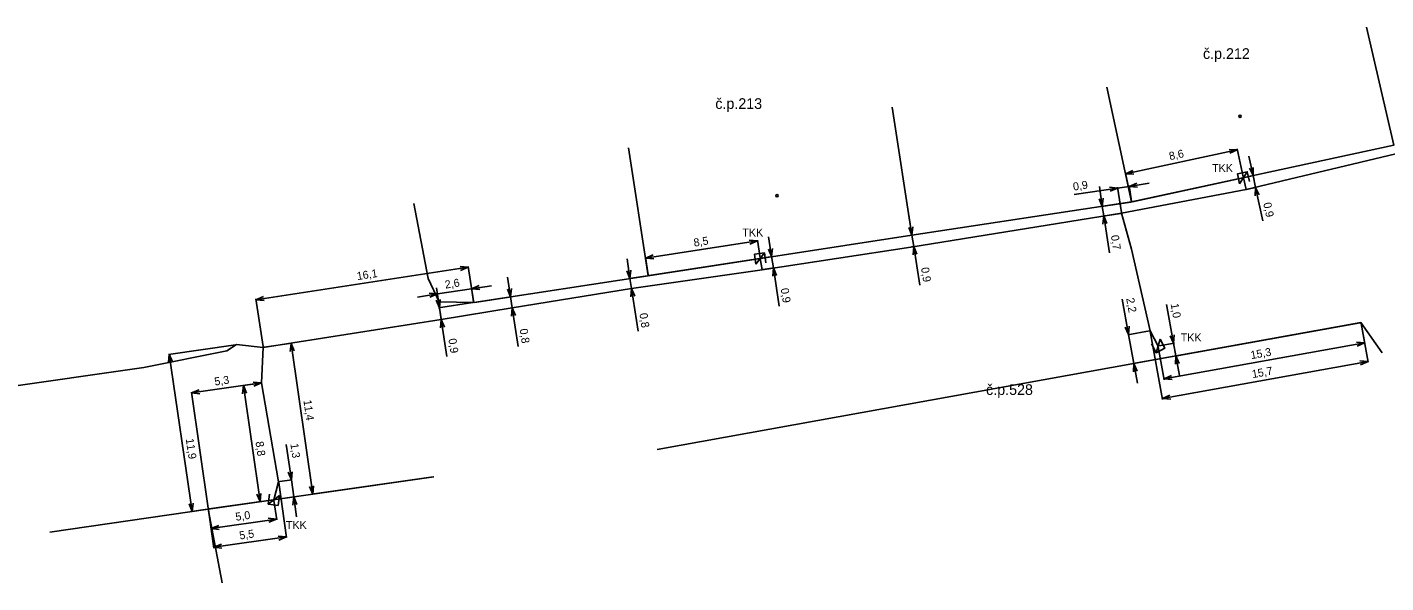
# Model space of a CAD drawing. Extents: x -770877 to -770229, y -1050342 to -1050226.
# Drawn here: x -770486.4 to -770384.5, y -1050339.6 to -1050298 of the extents above; entities that cross this region are included whole.
import ezdxf

# ---------------------------------------------------------------- set-up
doc = ezdxf.new("R2010")
doc.units = 0
for name, color, linetype in [('f001_pol_linie', 7, 'Continuous'), ('f001_pol_znacky', 7, 'Continuous'), ('f003_opt_sit_texty', 7, 'Continuous'), ('f003_opt_sit_znacky', 7, 'Continuous'), ('f006_osa_trasy', 7, 'Continuous'), ('f006_stp_koty', 7, 'Continuous'), ('Inspire adresy', 7, 'Continuous')]:
    doc.layers.add(name, color=color, linetype=linetype)

msp = doc.modelspace()

# ---------------------------------------------------------------- linework, layer by layer
at = {"layer": 'f001_pol_linie'}
for points in [[(-770405.45, -1050302.49), (-770403.58, -1050311.09), (-770383.92, -1050306.82), (-770385.97, -1050297.98)], [(-770441.3, -1050307.04), (-770439.82, -1050316.62), (-770420.05, -1050313.57), (-770421.53, -1050303.99)], [(-770457.38, -1050311.2), (-770456.32, -1050316.84), (-770455.49, -1050318.59), (-770452.9, -1050318.63), (-770439.82, -1050316.62)], [(-770420.05, -1050313.57), (-770403.58, -1050311.09)], [(-770384.81, -1050322.39), (-770386.39, -1050320.13), (-770439.15, -1050329.65)], [(-770455.89, -1050331.7), (-770472.8, -1050334.12), (-770471.76, -1050339.65)], [(-770472.8, -1050334.12), (-770484.69, -1050335.85)]]:
    msp.add_lwpolyline(points, dxfattribs=at)
at = {"layer": 'f001_pol_znacky'}
for centre in [(-770395.45, -1050304.66), (-770430.16, -1050310.62)]:
    msp.add_circle(centre, 0.0875, dxfattribs=at)
at = {"layer": 'f003_opt_sit_znacky'}
for p, q in [((-770395.49, -1050309.72), (-770394.91, -1050308.82)), ((-770431.75, -1050315.75), (-770431.11, -1050314.91)), ((-770401.43, -1050321.38), (-770401.75, -1050322.4)), ((-770467.47, -1050333.1), (-770468.31, -1050333.74))]:
    msp.add_line(p, q, dxfattribs=at)
for points in [[(-770394.75, -1050309.56), (-770394.91, -1050308.82), (-770395.65, -1050308.98), (-770395.49, -1050309.72)], [(-770431.01, -1050315.65), (-770431.11, -1050314.91), (-770431.85, -1050315.01), (-770431.75, -1050315.75)], [(-770402.1, -1050321.73), (-770401.75, -1050322.4), (-770401.08, -1050322.05), (-770401.43, -1050321.38)], [(-770468.21, -1050333), (-770468.31, -1050333.74), (-770467.57, -1050333.84), (-770467.47, -1050333.1)]]:
    msp.add_lwpolyline(points, dxfattribs=at)
at = {"layer": 'f006_osa_trasy'}
for points in [[(-770395, -1050310.16), (-770383.78, -1050307.48), (-770370.36, -1050301.17)], [(-770404.34, -1050311.94), (-770395, -1050310.16), (-770395.2, -1050309.27)], [(-770431.29, -1050316.17), (-770420.14, -1050314.47), (-770404.34, -1050311.94), (-770403.6, -1050314.62), (-770402.19, -1050320.74), (-770401.59, -1050321.89)], [(-770431.29, -1050316.17), (-770431.43, -1050315.33)], [(-770468.68, -1050321.99), (-770455.33, -1050319.91), (-770450.01, -1050319.03), (-770441.07, -1050317.58), (-770431.29, -1050316.17)], [(-770612.67, -1050337.51), (-770606.25, -1050337.99), (-770603.63, -1050338.43), (-770599.28, -1050338.53), (-770590.33, -1050338.05), (-770576.49, -1050336.75), (-770554.21, -1050334.08), (-770551.62, -1050334.25), (-770534.12, -1050331.71), (-770510.63, -1050328.23), (-770477.63, -1050323.5), (-770471.41, -1050322.26), (-770470.69, -1050321.78), (-770468.68, -1050321.99)], [(-770468.68, -1050321.99), (-770468.81, -1050324.66), (-770467.53, -1050332.07), (-770467.89, -1050333.42)]]:
    msp.add_lwpolyline(points, dxfattribs=at)
at = {"layer": 'f006_stp_koty'}
for p, q in [((-770395.66, -1050307.17), (-770404.04, -1050308.99)), ((-770395.21, -1050309.21), (-770395.67, -1050307.11)), ((-770394.8, -1050307.65), (-770394.48, -1050309.11)), ((-770403.59, -1050311.03), (-770404.05, -1050308.93)), ((-770403.59, -1050311.03), (-770403.77, -1050309.86)), ((-770402.27, -1050309.69), (-770403.76, -1050309.92)), ((-770403.52, -1050311.08), (-770394.42, -1050309.1)), ((-770394.29, -1050310), (-770394.48, -1050309.11)), ((-770407.89, -1050310.54), (-770404.63, -1050310.05)), ((-770406, -1050309.94), (-770405.78, -1050311.42)), ((-770403.76, -1050309.92), (-770404.63, -1050310.05)), ((-770404.35, -1050311.88), (-770404.63, -1050309.99)), ((-770394.94, -1050310.15), (-770394.23, -1050309.99)), ((-770393.74, -1050312.5), (-770394.29, -1050310)), ((-770403.64, -1050311.1), (-770405.84, -1050311.43)), ((-770405.67, -1050312.14), (-770405.78, -1050311.42)), ((-770420.28, -1050312.09), (-770420.05, -1050313.57)), ((-770404.4, -1050311.95), (-770405.73, -1050312.15)), ((-770405.25, -1050314.91), (-770405.67, -1050312.14)), ((-770431.44, -1050315.27), (-770431.64, -1050313.95)), ((-770430.8, -1050313.71), (-770430.57, -1050315.19)), ((-770419.92, -1050314.44), (-770420.05, -1050313.57)), ((-770431.63, -1050314.01), (-770440.02, -1050315.3)), ((-770420.08, -1050314.46), (-770419.86, -1050314.43)), ((-770419.47, -1050317.33), (-770419.92, -1050314.44)), ((-770469.23, -1050318.42), (-770453.31, -1050315.98)), ((-770452.92, -1050318.51), (-770453.32, -1050315.92)), ((-770441.41, -1050315.35), (-770441.19, -1050316.83)), ((-770439.83, -1050316.56), (-770440.03, -1050315.24)), ((-770439.76, -1050316.61), (-770430.51, -1050315.18)), ((-770430.44, -1050316.04), (-770430.57, -1050315.19)), ((-770450.36, -1050316.72), (-770450.14, -1050318.21)), ((-770439.88, -1050316.63), (-770441.24, -1050316.84)), ((-770441.07, -1050317.58), (-770441.19, -1050316.83)), ((-770431.23, -1050316.16), (-770430.38, -1050316.03)), ((-770430, -1050318.9), (-770430.44, -1050316.04)), ((-770457.11, -1050318.22), (-770455.62, -1050317.99)), ((-770455.69, -1050317.54), (-770455.47, -1050319.02)), ((-770455.34, -1050319.85), (-770455.63, -1050317.93)), ((-770453.06, -1050317.6), (-770455.62, -1050317.99)), ((-770452.91, -1050318.57), (-770453.07, -1050317.54)), ((-770451.58, -1050317.37), (-770453.06, -1050317.6)), ((-770440.58, -1050320.77), (-770441.07, -1050317.58)), ((-770468.69, -1050321.93), (-770469.24, -1050318.36)), ((-770452.96, -1050318.64), (-770455.53, -1050319.03)), ((-770455.33, -1050319.91), (-770455.47, -1050319.02)), ((-770452.84, -1050318.62), (-770450.08, -1050318.2)), ((-770450.01, -1050319.03), (-770450.14, -1050318.21)), ((-770449.56, -1050321.93), (-770450.01, -1050319.03)), ((-770404.28, -1050318.39), (-770403.81, -1050321.03)), ((-770400.96, -1050318.79), (-770400.43, -1050321.68)), ((-770454.91, -1050322.67), (-770455.33, -1050319.91)), ((-770402.25, -1050320.75), (-770403.86, -1050321.04)), ((-770403.81, -1050321.03), (-770403.41, -1050323.2)), ((-770386.45, -1050320.14), (-770403.47, -1050323.21)), ((-770402.18, -1050320.8), (-770401.26, -1050325.89)), ((-770386.45, -1050320.14), (-770400.32, -1050322.64)), ((-770386.38, -1050320.19), (-770386.11, -1050321.71)), ((-770386.38, -1050320.19), (-770385.85, -1050323.11)), ((-770470.75, -1050321.79), (-770475.78, -1050322.52)), ((-770468.62, -1050321.98), (-770466.53, -1050321.68)), ((-770466.59, -1050321.69), (-770464.97, -1050333)), ((-770401.58, -1050321.95), (-770401.13, -1050324.42)), ((-770401.53, -1050321.88), (-770400.37, -1050321.67)), ((-770386.12, -1050321.65), (-770401.14, -1050324.36)), ((-770400.43, -1050321.68), (-770400.26, -1050322.63)), ((-770475.72, -1050322.51), (-770474.01, -1050334.3)), ((-770385.86, -1050323.05), (-770401.27, -1050325.83)), ((-770400, -1050324.11), (-770400.26, -1050322.63)), ((-770403.15, -1050324.68), (-770403.41, -1050323.2)), ((-770474.05, -1050325.41), (-770468.81, -1050324.66)), ((-770468.87, -1050324.67), (-770470.22, -1050324.86)), ((-770470.16, -1050324.85), (-770468.92, -1050333.56)), ((-770472.81, -1050334.06), (-770474.06, -1050325.35)), ((-770466.95, -1050329.27), (-770466.57, -1050331.93)), ((-770467.52, -1050332.13), (-770466.93, -1050336.26)), ((-770467.47, -1050332.06), (-770466.51, -1050331.92)), ((-770466.57, -1050331.93), (-770466.39, -1050333.2)), ((-770455.95, -1050331.71), (-770465.03, -1050333.01)), ((-770472.74, -1050334.11), (-770466.33, -1050333.19)), ((-770466.18, -1050334.69), (-770466.39, -1050333.2)), ((-770472.86, -1050334.13), (-770474.07, -1050334.3)), ((-770472.79, -1050334.18), (-770472.59, -1050335.63)), ((-770472.79, -1050334.18), (-770472.38, -1050337.04)), ((-770472.74, -1050334.11), (-770468.86, -1050333.56)), ((-770467.88, -1050333.48), (-770467.67, -1050334.93)), ((-770472.6, -1050335.57), (-770467.68, -1050334.87)), ((-770472.39, -1050336.98), (-770466.94, -1050336.2))]:
    msp.add_line(p, q, dxfattribs=at)
for points in [[(-770396.28, -1050307.15), (-770395.66, -1050307.17), (-770396.21, -1050307.44)], [(-770403.42, -1050309.01), (-770404.04, -1050308.99), (-770403.48, -1050308.72)], [(-770394.46, -1050308.5), (-770394.48, -1050309.11), (-770394.75, -1050308.56)], [(-770403.14, -1050309.97), (-770403.76, -1050309.92), (-770403.19, -1050309.68)], [(-770405.72, -1050310.81), (-770405.78, -1050311.42), (-770406.01, -1050310.85)], [(-770405.24, -1050309.99), (-770404.63, -1050310.05), (-770405.2, -1050310.28)], [(-770394.31, -1050310.62), (-770394.29, -1050310), (-770394.01, -1050310.56)], [(-770405.73, -1050312.76), (-770405.67, -1050312.14), (-770405.43, -1050312.71)], [(-770419.99, -1050312.95), (-770420.05, -1050313.57), (-770420.29, -1050313)], [(-770432.25, -1050313.95), (-770431.63, -1050314.01), (-770432.2, -1050314.25)], [(-770430.51, -1050314.58), (-770430.57, -1050315.19), (-770430.81, -1050314.62)], [(-770419.97, -1050315.05), (-770419.92, -1050314.44), (-770419.68, -1050315.01)], [(-770453.92, -1050315.92), (-770453.31, -1050315.98), (-770453.88, -1050316.22)], [(-770439.41, -1050315.36), (-770440.02, -1050315.3), (-770439.45, -1050315.06)], [(-770441.13, -1050316.21), (-770441.19, -1050316.83), (-770441.42, -1050316.26)], [(-770430.49, -1050316.65), (-770430.44, -1050316.04), (-770430.2, -1050316.61)], [(-770456.24, -1050317.93), (-770455.62, -1050317.99), (-770456.19, -1050318.23)], [(-770452.44, -1050317.65), (-770453.06, -1050317.6), (-770452.49, -1050317.36)], [(-770450.08, -1050317.59), (-770450.14, -1050318.21), (-770450.38, -1050317.64)], [(-770441.13, -1050318.2), (-770441.07, -1050317.58), (-770440.83, -1050318.15)], [(-770468.61, -1050318.48), (-770469.23, -1050318.42), (-770468.66, -1050318.18)], [(-770455.41, -1050318.41), (-770455.47, -1050319.02), (-770455.71, -1050318.45)], [(-770450.07, -1050319.65), (-770450.01, -1050319.03), (-770449.77, -1050319.6)], [(-770455.39, -1050320.53), (-770455.33, -1050319.91), (-770455.09, -1050320.48)], [(-770403.76, -1050320.41), (-770403.81, -1050321.03), (-770404.06, -1050320.47)], [(-770400.39, -1050321.06), (-770400.43, -1050321.68), (-770400.69, -1050321.12)], [(-770466.65, -1050322.31), (-770466.59, -1050321.69), (-770466.35, -1050322.26)], [(-770386.73, -1050321.61), (-770386.12, -1050321.65), (-770386.68, -1050321.9)], [(-770475.78, -1050323.13), (-770475.72, -1050322.51), (-770475.48, -1050323.08)], [(-770400.3, -1050323.25), (-770400.26, -1050322.63), (-770400.01, -1050323.2)], [(-770386.48, -1050323.01), (-770385.86, -1050323.05), (-770386.43, -1050323.3)], [(-770403.45, -1050323.82), (-770403.41, -1050323.2), (-770403.16, -1050323.77)], [(-770400.53, -1050324.4), (-770401.14, -1050324.36), (-770400.58, -1050324.11)], [(-770470.23, -1050325.47), (-770470.16, -1050324.85), (-770469.93, -1050325.43)], [(-770469.43, -1050324.6), (-770468.81, -1050324.66), (-770469.38, -1050324.89)], [(-770473.43, -1050325.47), (-770474.05, -1050325.41), (-770473.48, -1050325.18)], [(-770400.65, -1050325.87), (-770401.27, -1050325.83), (-770400.71, -1050325.57)], [(-770466.51, -1050331.32), (-770466.57, -1050331.93), (-770466.8, -1050331.36)], [(-770468.85, -1050332.95), (-770468.92, -1050333.56), (-770469.15, -1050332.99)], [(-770466.45, -1050333.82), (-770466.39, -1050333.2), (-770466.15, -1050333.78)], [(-770464.91, -1050332.38), (-770464.97, -1050333), (-770465.2, -1050332.43)], [(-770473.94, -1050333.68), (-770474.01, -1050334.3), (-770474.24, -1050333.72)], [(-770468.3, -1050334.81), (-770467.68, -1050334.87), (-770468.26, -1050335.1)], [(-770471.98, -1050335.64), (-770472.6, -1050335.57), (-770472.02, -1050335.34)], [(-770467.55, -1050336.14), (-770466.94, -1050336.2), (-770467.51, -1050336.44)], [(-770471.78, -1050337.05), (-770472.39, -1050336.98), (-770471.82, -1050336.75)]]:
    msp.add_lwpolyline(points, dxfattribs=at)

# ---------------------------------------------------------------- texts
at = {"layer": 'f003_opt_sit_texty'}
for p in [(-770397.55, -1050308.84), (-770432.76, -1050313.68), (-770399.9, -1050321.55), (-770466.98, -1050335.61)]:
    msp.add_text('TKK', height=0.6, dxfattribs=at).set_placement(p)
at = {"layer": 'f006_stp_koty'}
for s, rotation, p in [('8,6', 12.2675, (-770400.71, -1050307.96)), ('0,9', 8.5631, (-770407.93, -1050310.24)), ('0,9', 282.2539, (-770393.72, -1050311.19)), ('8,5', 8.7821, (-770436.37, -1050314.44)), ('0,7', 278.5631, (-770405.14, -1050313.61)), ('16,1', 8.7363, (-770461.62, -1050316.95)), ('2,6', 8.7363, (-770455.02, -1050317.59)), ('0,9', 278.7701, (-770419.37, -1050316.03)), ('0,9', 278.7701, (-770429.89, -1050317.59)), ('2,2', 280.2268, (-770403.99, -1050318.33)), ('1,0', 280.2268, (-770400.66, -1050318.74)), ('0,8', 278.7363, (-770440.48, -1050319.46)), ('0,8', 278.7363, (-770449.46, -1050320.63)), ('0,9', 278.7363, (-770454.8, -1050321.37)), ('15,3', 10.2268, (-770394.61, -1050322.88)), ('5,3', 8.1454, (-770472.3, -1050324.86)), ('15,7', 10.2268, (-770394.51, -1050324.3)), ('11,4', 278.1454, (-770465.67, -1050325.97)), ('11,9', 278.2643, (-770474.49, -1050328.86)), ('8,8', 278.1454, (-770469.26, -1050329.08)), ('1,3', 278.1454, (-770466.65, -1050329.23)), ('5,0', 8.1454, (-770470.72, -1050335)), ('5,5', 8.1454, (-770470.43, -1050336.4))]:
    msp.add_text(s, height=0.6, rotation=rotation, dxfattribs=at).set_placement(p)
at = {"layer": 'Inspire adresy'}
for s, p in [('č.p.212', (-770398.23, -1050300.36)), ('č.p.213', (-770434.79, -1050304.11)), ('č.p.528', (-770414.49, -1050325.56))]:
    msp.add_text(s, height=0.8, dxfattribs=at).set_placement(p)

doc.saveas('drawing.dxf')
